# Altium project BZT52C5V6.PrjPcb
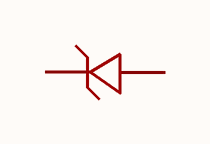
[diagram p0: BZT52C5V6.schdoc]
1 sheet, 1 parts. Net scope: global (net labels, ports and power ports of the same name join across sheets).

## Sheet BZT52C5V6.schdoc
size 127 x 101 mm

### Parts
ZD?  bzt52c5v6_c2119  [SOD-123_L2.8-W1.8-LS3.7-RD]  (value not drawn)

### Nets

Not connected (* = marked no-connect by the designer): ZD? 1(K) 2(A)

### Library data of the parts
ZD? = bzt52c5v6_c2119: 二极管配置:1个独立式;稳压值(标称值):5.6V;稳压值(范围值):5.2V~6V;耗散功率(Pd):500mW;; Manufacturer: CJ(江苏长电/长晶); AddInBom: yes; ModelId: 7884390a25fb4c08947731ebfba7e3f8; ModelTransform: 144.8816,62.992,0,0,0,0,0,0,0; Diode Configuration: 1个独立式; Zener Voltage(Nom): 5.6V; Reverse Leakage Current (Ir): 1uA; Pd - Power Dissipation: 500mW; Impedance(Zzt): 40Ω; Impedance(Zzk): 400Ω; Operating Junction Temperature Range: -55℃~+150℃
